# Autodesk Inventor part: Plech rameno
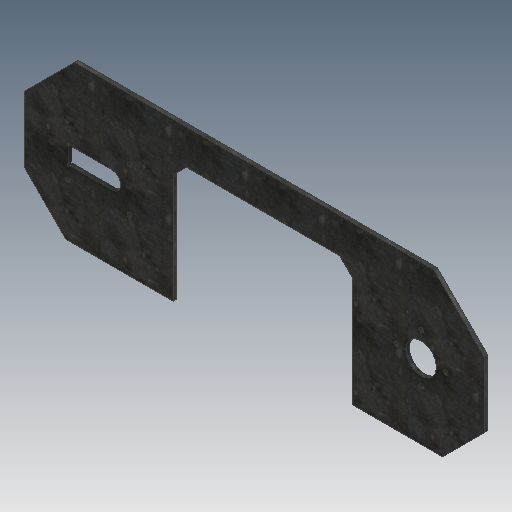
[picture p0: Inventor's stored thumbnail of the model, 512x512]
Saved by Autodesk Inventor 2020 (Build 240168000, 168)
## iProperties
Created: 2025-03
Part Number: Plech rameno
Material: Ocel
Document SubType Name: Modeling
Designer: doma
Density: 7.85 g/cm^3
Appearance: Plech
Mass: 14606.2 g
Surface Area: 4964.6 cm^2
Volume: 1860.67 cm^3
Author: doma
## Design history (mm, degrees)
sketch "Náčrt1"
  geometry: L1 (1513.721, 322.322)-(1513.721, 397.322); L2 (1513.721, 322.322)-(1513.721, 247.322); L3 (2563.721, 322.322)-(2563.721, 397.322); L4 (2563.721, 322.322)-(2563.721, 247.322); L5 (1663.721, 152.322)-(1608.721, 152.322); L6 (1663.721, 152.322)-(1853.721, 152.322); L7 (2263.721, 152.322)-(2468.721, 152.322); L8 (2263.721, 322.322)-(2263.721, 255.322); L9 (2233.721, 432.322)-(1883.721, 432.322); L10 (2263.721, 402.322)-(2233.721, 432.322); L11 (2263.721, 322.322)-(2263.721, 402.322); L12 (1853.721, 322.322)-(1853.721, 402.322); L13 (1883.721, 432.322)-(1853.721, 402.322); L14 (1853.721, 322.322)-(1853.721, 152.322); L15 (1513.721, 397.322)-(1628.721, 512.322); L16 (2563.721, 397.322)-(2448.721, 512.322); L17 (1513.721, 247.322)-(1608.721, 152.322); L18 (2563.721, 247.322)-(2468.721, 152.322); L19 (1663.721, 342.322)-(1703.721, 342.322); L20 (1663.721, 302.322)-(1703.721, 302.322); L21 (2058.721, 512.322)-(1628.721, 512.322); L22 (2058.721, 512.322)-(2448.721, 512.322); L23 (1703.721, 342.322)-(1713.721, 342.322); L24 (1703.721, 302.322)-(1713.721, 302.322); L25 (1653.721, 342.322)-(1663.721, 342.322); L26 (1653.721, 302.322)-(1663.721, 302.322); L27 (2263.721, 255.322)-(2263.721, 152.322); C1 r 5.5 at (2419.721, 378.322); C2 r 5.5 at (2475.721, 322.322); C3 r 5.5 at (2419.721, 266.322); C4 r 5.5 at (2363.721, 322.322); C5 r 35 at (2419.721, 322.322); C6 r 5.5 at (1613.721, 272.322); C7 r 5.5 at (1753.721, 272.322); C8 r 5.5 at (1613.721, 372.322); C9 r 5.5 at (1753.721, 372.322); A1 r 20 centre (1653.721, 322.322) between (1653.721, 342.322) and (1653.721, 302.322); A2 r 20 centre (1713.721, 322.322) between (1713.721, 302.322) and (1713.721, 342.322); 30 further points
  constraints: 54 end point, 11 centre point, 4 point on circle
extrude "Vysunutí1" new body sketch "Náčrt1" distance "d54" = 8; taper "d55" = 0 deg
sketch "Náčrt2"
  geometry: L1 (-1653.721, 342.322)-(-1616.221, 342.322); L2 (-1613.721, 339.822)-(-1613.721, 304.822); L3 (-1713.721, 302.322)-(-1653.721, 302.322) reference; L4 (-1616.221, 302.322)-(-1653.721, 302.322); A1 r 20 centre (-1653.721, 322.322) between (-1653.721, 302.322) and (-1653.721, 342.322) reference; A2 r 2.5 centre (-1613.721, 342.322) between (-1613.721, 339.822) and (-1616.221, 342.322); A3 r 2.5 centre (-1613.721, 302.322) between (-1616.221, 302.322) and (-1613.721, 304.822); 1 further point
  constraints: 6 end point, 4 point on circle, 2 centre point, 2 perpendicular, 1 horizontal
  dimensions: "d56" = 5 diameter of A2; "d57" = 5 diameter of A3
extrude "Vysunutí2" cut sketch "Náčrt2" distance "d58" = 10; taper "d59" = 0 deg
node "Těleso1"
